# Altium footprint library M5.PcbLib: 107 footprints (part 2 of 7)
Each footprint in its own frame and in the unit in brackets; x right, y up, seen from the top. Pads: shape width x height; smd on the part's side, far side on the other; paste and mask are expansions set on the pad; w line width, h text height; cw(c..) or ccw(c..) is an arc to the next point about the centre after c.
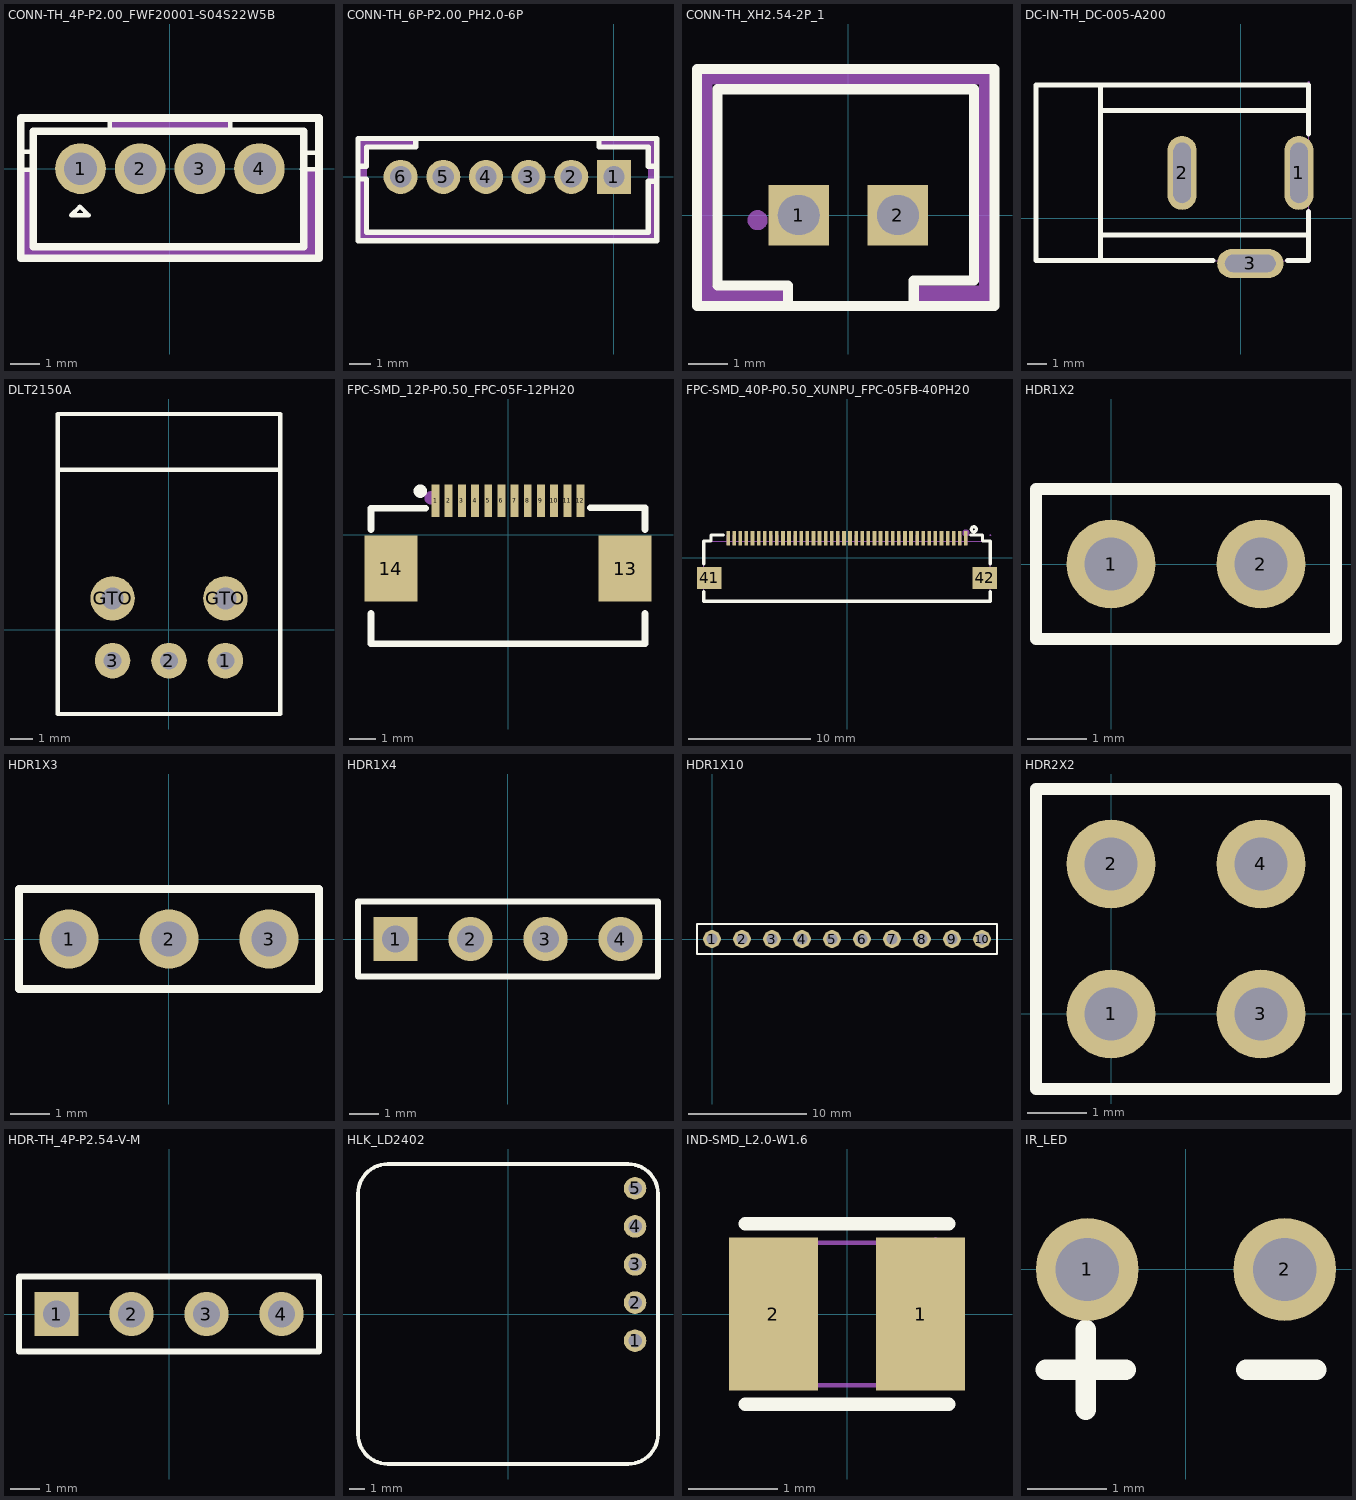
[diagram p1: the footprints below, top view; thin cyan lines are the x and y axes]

## CONN-TH_4P-P2.00_FWF20001-S04S22W5B [mm]
pads (4):
  round 1.7 hole 1.1: 1(-3,0) 2(-1,0) 3(1,0) 4(3,0)
Top Overlay:
  lines w0.15: -5,-0.03 -4.63,-0.03 ; -5,0.57 -4.59,0.57 ; -2.02,1.24 -2.02,1.7 ; 2.02,1.25 2.02,1.7 ; 4.42,-0.02 5,-0.02 ; 4.47,0.54 5,0.54 ; -3.31,-1.56 -3.02,-1.27 -2.72,-1.57 -3.31,-1.56
  lines w0.254: -5,-3 5,-3 5,1.7 -5,1.7 -5,-3 ; -4.59,-2.62 -4.59,1.25 4.49,1.25 4.49,-2.62 -4.59,-2.62
Mechanical 6:
  region: 4.42,-0.02 4.99,-0.02 5,-0.03 5,-3 -5,-3 -5,-0.03 -4.63,-0.03 -4.63,-2.6 -4.62,-2.61 4.4,-2.61 4.45,-2.56
  region: -2.02,1.35 2,1.35 2.02,1.33 2.02,1.69 2.01,1.7 -2.02,1.7
Mechanical 15:
  region: -2.75,-0.25 -3.25,-0.25 -3.25,0.25 -2.75,0.25
  region: -0.75,-0.25 -1.25,-0.25 -1.25,0.25 -0.75,0.25
  region: 1.25,-0.25 0.75,-0.25 0.75,0.25 1.25,0.25
  region: 3.25,-0.25 2.75,-0.25 2.75,0.25 3.25,0.25
  region: -4.935,-3 -4.954,-3.046 -5,-3.065 -5.046,-3.046 -5.065,-3 -5.046,-2.954 -5,-2.935 -4.954,-2.954
  lines w0.051: -5,-3 -5,1.7 5,1.7 5,-3 -5,-3
3D body: height 6.02, standoff -3.48, extent -5.03,-3.079 5.03,1.651

## CONN-TH_6P-P2.00_PH2.0-6P [mm]
pads (6):
  rect 1.6x1.6 hole 1: 1(0,0)
  round 1.6 hole 1: 2(-2,0) 3(-4,0) 4(-6,0) 5(-8,0) 6(-10,0)
Top Overlay:
  lines w0.254: -12,-0.1 -11.6,-0.1 -11.6,-2.6 1.6,-2.6 1.6,-0.2 2,-0.2 ; -12,0.5 -11.6,0.5 -11.6,1.4 -9.3,1.4 -9.3,1.8 ; -0.7,1.8 -0.7,1.4 1.6,1.4 1.6,0.5 2,0.5 ; 2,-0.2 2,-3 -12,-3 -12,1.8 2,1.8 2,-0.2
Mechanical 6:
  region: -0.7,1.8 -0.7,1.4 1.6,1.4 1.6,-2.6 -11.6,-2.6 -11.6,1.4 -9.3,1.4 -9.3,1.8 -12,1.8 -12,-3 2,-3 2,1.8
Mechanical 15:
  region: 2.065,1.8 2.046,1.754 2,1.735 1.954,1.754 1.935,1.8 1.954,1.846 2,1.865 2.046,1.846
  region: -10.25,0.25 -9.75,0.25 -9.75,-0.25 -10.25,-0.25
  region: -8.25,0.25 -7.75,0.25 -7.75,-0.25 -8.25,-0.25
  region: -6.25,0.25 -5.75,0.25 -5.75,-0.25 -6.25,-0.25
  region: -4.25,0.25 -3.75,0.25 -3.75,-0.25 -4.25,-0.25
  region: -2.25,0.25 -1.75,0.25 -1.75,-0.25 -2.25,-0.25
  region: -0.25,0.25 0.25,0.25 0.25,-0.25 -0.25,-0.25
  lines w0.051: -12,-3 2,-3 2,1.8 -12,1.8 -12,-3
3D body: height 6.18, standoff -4.43, extent -11.993,-3.022 2.087,1.778

## CONN-TH_XH2.54-2P_1 [mm]
pads (2):
  rect 1.524x1.524 hole 1 slot 1.05 at 0 deg paste+0 mask+0.05: 1(-1.25,0) 2(1.25,0)
Top Overlay:
  lines w0.254: -1.524,-2.286 -1.524,-1.778 -1.651,-1.778 -3.302,-1.778 -3.302,3.175 3.175,3.175 3.175,-1.651 1.651,-1.651 1.651,-2.159 ; -3.81,-2.286 -3.81,3.683 3.683,3.683 3.683,-2.286 -3.81,-2.286
Mechanical 6:
  circle w0.254: c-2.286,-0.127 r0.127
  region: -1.524,-1.778 -1.524,-2.159 -3.81,-2.159 -3.81,3.683 3.683,3.683 3.683,-2.159 1.651,-2.159 1.651,-1.778 3.302,-1.778 3.302,3.302 -3.429,3.302 -3.429,-1.778
Mechanical 15:
  region: -1.555,0.305 -0.945,0.305 -0.945,-0.305 -1.555,-0.305
  region: 0.945,0.305 1.555,0.305 1.555,-0.305 0.945,-0.305
  region: -3.685,-2.3 -3.704,-2.346 -3.75,-2.365 -3.796,-2.346 -3.815,-2.3 -3.796,-2.254 -3.75,-2.235 -3.704,-2.254
  lines w0.051: -3.75,-2.3 3.75,-2.3 3.75,3.5 -3.75,3.5 -3.75,-2.3
3D body: height 7.08, standoff -3.4, extent -3.81,-2.286 3.73,3.564

## DC-IN-TH_DC-005-A200 [mm]
pads (3):
  oval 1.5x3.8 hole 0.9 slot 3.1 at 90 deg copper offset -0.001,0: 1(3,2.325)
  oval 1.5x3.8 hole 0.9 slot 3.1 at 90 deg copper offset 0,0: 2(-3,2.325)
  oval 3.4x1.5 hole 0.9 slot 2.6 at 0 deg copper offset 0,-0.001: 3(0.499,-2.325)
Top Overlay:
  lines w0.254: -7.2,-2.175 -7.2,6.825 ; -7.121,-0.875 3.499,-0.875 ; -7.121,5.525 3.499,5.525 ; -1.42,-2.175 -10.5,-2.175 -10.5,6.825 3.499,6.825 3.499,4.318 ; 2.419,-2.175 3.499,-2.175 3.499,0.332
Mechanical 15:
  region: -0.35,-1.965 1.349,-1.965 1.349,-2.685 -0.35,-2.685
  region: -2.64,3.425 -2.64,1.225 -3.36,1.225 -3.36,3.425
  region: 2.64,1.225 2.64,3.425 3.36,3.425 3.36,1.225
  region: 3.564,6.952 3.545,6.906 3.499,6.887 3.453,6.906 3.434,6.952 3.453,6.998 3.499,7.017 3.545,6.998
  lines w0.051: -10.501,-2.175 -10.501,6.825 3.499,6.825 3.499,-2.175 -10.501,-2.175
3D body: height 11.01, standoff -4, extent -10.373,-2.609 3.527,6.691

## DLT2150A [mm]
pads (5):
  round 1.6 hole 0.8: 1(2.54,-1.4) 2(0,-1.4) 3(-2.54,-1.4)
  round 2 hole 1: GTO(-2.54,1.4) GTO(2.54,1.4)
Top Overlay:
  lines w0.2: -5,7.2 5,7.2 ; -5,-3.8 -5,9.7 5,9.7 5,-3.8 -5,-3.8

## FPC-SMD_12P-P0.50_FPC-05F-12PH20 [mm]
pads (14):
  rect 0.3x1.25 smd paste+0 mask+0.05: 1(-2.75,1.288) 2(-2.25,1.288) 3(-1.75,1.288) 4(-1.25,1.288) 5(-0.75,1.288) 6(-0.25,1.288) 7(0.25,1.288) 8(0.75,1.288) 9(1.25,1.288) 10(1.75,1.288) 11(2.25,1.288) 12(2.75,1.288)
  rect 2x2.5 smd paste+0 mask+0.05: 13(4.44,-1.288) 14(-4.44,-1.288)
Top Overlay:
  circle w0.254: c-3.327,1.651 r0.127
  lines w0.254: -5.2,-2.993 -5.2,-4.137 5.2,-4.137 5.2,-2.993 ; -5.2,0.194 -5.2,1 -3.131,1 ; 3.131,1.016 5.2,1.016 5.2,0.194
Mechanical 6:
  circle w0.254: c-2.921,1.397 r0.127
3D body: height 1.97, standoff -0.08, extent -5.21,-4.14 5.21,1.78

## FPC-SMD_40P-P0.50_XUNPU_FPC-05FB-40PH20 [mm]
pads (42):
  rect 0.3x1.2 smd paste+0 mask+0.05: 1(9.75,1.625) 2(9.25,1.625) 3(8.75,1.625) 4(8.25,1.625) 5(7.75,1.625) 6(7.25,1.625) 7(6.75,1.625) 8(6.25,1.625) 9(5.75,1.625) 10(5.25,1.625) 11(4.75,1.625) 12(4.25,1.625) 13(3.75,1.625) 14(3.25,1.625) 15(2.75,1.625) 16(2.25,1.625) 17(1.75,1.625) 18(1.25,1.625) 19(0.75,1.625) 20(0.25,1.625) 21(-0.25,1.625) 22(-0.75,1.625) 23(-1.25,1.625) 24(-1.75,1.625) 25(-2.25,1.625) 26(-2.75,1.625) 27(-3.25,1.625) 28(-3.75,1.625) 29(-4.25,1.625) 30(-4.75,1.625) 31(-5.25,1.625) 32(-5.75,1.625) 33(-6.25,1.625) 34(-6.75,1.625) 35(-7.25,1.625) 36(-7.75,1.625) 37(-8.25,1.625) 38(-8.75,1.625) 39(-9.25,1.625) 40(-9.75,1.625)
  rect 2x1.8 smd paste+0 mask+0.05: 41(-11.3,-1.625) 42(11.3,-1.625)
Top Overlay:
  circle w0.254: c10.399,2.355 r0.209
  lines w0.254: -11.75,-2.756 -11.75,-3.55 11.75,-3.55 11.75,-2.756 ; -11.75,-0.494 -11.75,1.1 ; -11.75,0.95 -11.75,1.4 -11.15,1.4 -11.15,1.9 -10.131,1.9 ; 10.131,1.9 11.1,1.9 11.1,1.4 11.75,1.4 11.75,-0.494
Mechanical 6:
  circle w0.3: c9.75,2.05 r0.15
Mechanical 15:
  drawing of 47 lines, arcs and shapes, not listed

## HDR1X2 [mm] "Connector; Header; 2 Position"
pads (2):
  round 1.5 hole 0.9: 1(0,0) 2(2.54,0)
Top Overlay:
  lines w0.2: -1.27,-1.27 3.81,-1.27 3.81,1.27 -1.27,1.27 -1.27,-1.27
3D body: height 8.52, standoff -2.98, extent -1.17,-1.23 3.71,1.27

## HDR1X3 [mm] "Connector; Header; 3 Position"
pads (3):
  round 1.5 hole 0.9: 1(-2.54,0) 2(0,0) 3(2.54,0)
Top Overlay:
  lines w0.2: -3.81,-1.27 -3.81,1.27 3.81,1.27 3.81,-1.27 -3.81,-1.27
3D body: height 8.52, standoff -2.98, extent -3.685,-1.176 3.735,1.324

## HDR1X4 [mm]
pads (4):
  rect 1.5x1.5 hole 0.9: 1(-3.81,0)
  round 1.5 hole 0.9: 2(-1.27,0) 3(1.27,0) 4(3.81,0)
Top Overlay:
  lines w0.2: -5.08,-1.27 -5.08,1.27 5.08,1.27 5.08,-1.27 -5.08,-1.27
3D body: height 8.52, standoff -2.98, extent -5.007,-1.23 4.953,1.27

## HDR1X10 [mm] "Connector; Header; 10 Position"
pads (10):
  round 1.5 hole 0.9: 1(0,0) 2(2.54,0) 3(5.08,0) 4(7.62,0) 5(10.16,0) 6(12.7,0) 7(15.24,0) 8(17.78,0) 9(20.32,0) 10(22.86,0)
Top Overlay:
  lines w0.2: -1.27,-1.27 24.13,-1.27 24.13,1.27 0.635,1.27 -1.27,1.27 -1.27,-1.27

## HDR2X2 [mm] "Connector; Header; 2x2 Position"
pads (4):
  round 1.5 hole 0.9: 1(0,0) 2(0,2.54) 3(2.54,0) 4(2.54,2.54)
Top Overlay:
  lines w0.2: -1.27,-1.27 -1.27,3.81 3.81,3.81 3.81,-1.27 -1.27,-1.27

## HDR-TH_4P-P2.54-V-M [mm]
pads (4):
  rect 1.5x1.5 hole 0.9: 1(-3.81,0)
  round 1.5 hole 0.9: 2(-1.27,0) 3(1.27,0) 4(3.81,0)
Top Overlay:
  lines w0.2: -5.08,-1.27 5.08,-1.27 5.08,1.27 -5.08,1.27 -5.08,-1.27

## HLK_LD2402 [mm]
pads (5):
  round 1.5 hole 0.9: 1(8.47,-1.778) 2(8.47,0.762) 3(8.47,3.302) 4(8.47,5.842) 5(8.47,8.382)
Top Overlay:
  lines w0.254: -10,-7.998 ccw(c-8,-7.998) -8,-9.998 8,-9.998 ccw(c8,-7.998) 10,-7.998 10,8.002 ccw(c8,8.002) 8,10.002 -8,10.002 ccw(c-8,8.002) -10,8.002 -10,-7.998

## IND-SMD_L2.0-W1.6 [mm]
pads (2):
  rect 1x1.72 smd: 1(0.828,0) 2(-0.828,0)
Top Overlay:
  lines w0.152: -1.143,-1.016 1.143,-1.016 ; -1.143,1.016 1.143,1.016
Mechanical 15:
  region: -1,0.8 -0.4,0.8 -0.4,-0.8 -1,-0.8
  region: 0.4,0.8 1,0.8 1,-0.8 0.4,-0.8
  region: 1.065,0.8 1.046,0.754 1,0.735 0.954,0.754 0.935,0.8 0.954,0.846 1,0.865 1.046,0.846
  lines w0.051: -1,-0.8 1,-0.8 1,0.8 -1,0.8 -1,-0.8
3D body: height 1.8, standoff 0, extent -1.1,-0.911 1.1,0.889

## IR_LED [mm]
pads (2):
  round 1.3 hole 0.8: 1(-1.25,0) 2(1.25,0)
Top Overlay:
  lines w0.254: -1.778,-1.27 -0.762,-1.27 ; -1.27,-1.778 -1.27,-0.762 ; 0.762,-1.27 1.651,-1.27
